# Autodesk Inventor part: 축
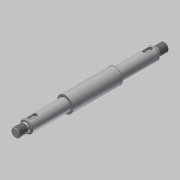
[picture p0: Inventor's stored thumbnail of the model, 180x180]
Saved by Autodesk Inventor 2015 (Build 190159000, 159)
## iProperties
Created: 2018-11
Part Number: 축
Material: 강철, 연강
Document SubType Name: Modeling
Designer: mduedu
Density: 1 g/cm^3
Appearance: 강철
Author: mduedu
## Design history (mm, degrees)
sketch "스케치1"
  geometry: L1 (-35, 0)-(35, 0); L2 (35, 0)-(35, 11); L3 (35, 11)-(-35, 11); L4 (-35, 11)-(-35, 0); L5 (-35, 0)-(-90, 0); L6 (-90, 0)-(-90, 8.5); L7 (-90, 8.5)-(-35, 8.5); L8 (-35, 8.5)-(-35, 0); L9 (-90, 0)-(-105, 0); L10 (-105, 0)-(-105, 6); L11 (-105, 6)-(-90, 6); L12 (-90, 6)-(-90, 0); L13 (0, 0)-(0, 11); L14 (35, 0)-(90, 0); L15 (90, 0)-(90, 8.5); L16 (90, 8.5)-(35, 8.5); L17 (35, 8.5)-(35, 0); L18 (90, 0)-(105, 0); L19 (105, 0)-(105, 6); L20 (105, 6)-(90, 6); L21 (90, 6)-(90, 0); 1 further point
  constraints: 42 end point, 6 parallel, 6 symmetric about line, 3 horizontal, 3 perpendicular, 2 midpoint, 1 coincident
  dimensions: "d0" = 22 diameter of L3 L1; "d2" = 17 diameter of L7 L5; "d3" = 12 diameter of L11 L9; "d4" = 70 distance of L2.end L3.end; "d5" = 55 distance of L6.end L7.end; "d6" = 210 distance between parallel lines of L19 L10
revolve "회전1" sketch "스케치1" stored, may be unused: angle "d7" = 90 deg
fillet "모깎기1" dims "d8" = 0.3
node "작업 평면1"
sketch "스케치2" dims "d11" = 12
  geometry: L1 (15, 2.5)-(22, 2.5); L2 (22, 2.5)-(22, -2.5); L3 (22, -2.5)-(15, -2.5); L4 (15, -2.5)-(15, 2.5); L5 (27.5, 8.5)-(27.5, -8.5) reference; 3 further points
  constraints: 8 end point, 2 midpoint, 2 parallel, 2 vertical alignment, 1 horizontal, 1 horizontal alignment, 1 perpendicular, 4 other
  dimensions: "d9" = 3 dimension on L5; "d10" = 5 distance between parallel lines of L3 L1
extrude "돌출1" cut sketch "스케치2" distance "d12" = 3; taper "d13" = 0 deg
chamfer "모따기1" distance "d14" = 1; stored, may be unused: second distance "d15" = 2, angle "d16" = 45 deg
feature "스레드1" dims "d17" = 12, "d18" = 0
feature "스레드2" dims "d19" = 12, "d20" = 0
chamfer "모따기2" distance "d21" = 1; stored, may be unused: second distance "d22" = 2, angle "d23" = 45 deg
node "솔리드1"
mirror "대칭1"
